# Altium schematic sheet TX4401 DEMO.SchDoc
size A
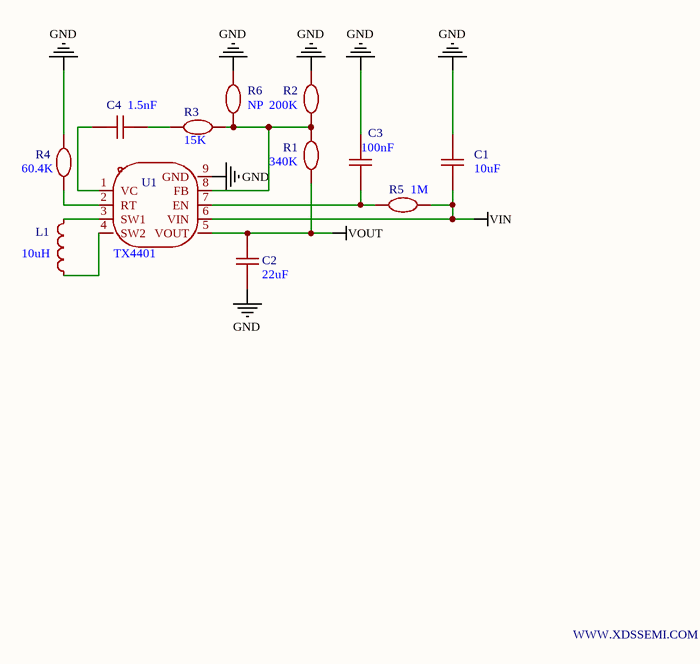
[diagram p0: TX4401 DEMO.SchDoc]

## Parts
C1  10uF  [C0603]
C2  22uF  [C0603]
C3  100nF  [C0603]
C4  1.5nF  [C0603]
L1  10uH  [IND-SMD_L5.4-W5.2_FXL0530]
R1  340K  [R0402]
R2  200K  [R0402]
R3  15K  [R0402]
R4  60.4K  [R0402]
R5  1M  [R0402]
R6  NP  [R0402]
U1  TX4401  [ESOP-8_L4.9-W3.9-P1.27-LS6.0-BL-EP-2]

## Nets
GND: C1.2 C2.1 C3.2 R2.2 R4.2 R6.2 U1.9(GND)
VIN: C1.1 R5.2 U1.6(VIN)
VOUT: C2.2 R1.2 U1.5(VOUT)
NetC3_1: C3.1 R5.1 U1.7(EN)
NetC4_1: C4.1 R3.2
NetC4_2: C4.2 U1.1(VC)
NetL1_1: L1.1 U1.4(SW2)
NetL1_2: L1.2 U1.3(SW1)
NetR1_1: R1.1 R2.1 R3.1 R6.1 U1.8(FB)
NetR4_1: R4.1 U1.2(RT)

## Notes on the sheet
- WWW.XDSSEMI.COM

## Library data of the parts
C1-C4 = FCC0603B104K500CT: Add into BOM: yes; Voltage Rating: 50V; Temperature Coefficient: X7R
L1 = FXL0530-100-M: Add into BOM: yes; Rated Current: 3.2A; Saturation Current (Isat): 3.5A
R1-R6 = WF04H1004BTL: Add into BOM: yes
U1 = TX4401: Add into BOM: yes; Output Current: 1A; Switching Frequency: 350kHz~1.5MHz; Quiescent Current (Iq): 1mA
